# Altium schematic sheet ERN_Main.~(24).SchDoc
size A; SheetNumber: 1; SheetTotal: 1; SPICEModelCacheDBTNACQE: <root> / <DocumentId>DBTNACQE</DocumentId> / <CacheFrame Number="0"> / <Model Name="1n5400" Kind="MDL"> / <Text>*1N5400 MCE / * 50V 3A Si Rectifier pkg:DO-201 1,2 / .MODEL 1N5400 D(IS=2.68E-12 RS=0.00977 N=1.17 TT=1.44E-5 CJO=1.24E-10 / + VJ=0.6 M=0.333 BV=66.6 IBV=1E-5 )</Text> / </Model> / <Model Name="led2" Kind="MDL"> / <Text>*Typ RED,GREEN,YELLOW,AMBER GaAs LED: Vf=2.1V Vr=4V If=40mA trr=3uS / *LED Pinout: 1=A, 2=K / .MODEL LED2 D (IS=93.1P RS=42M N=4.61 BV=4 IBV=10U / + CJO=2.97P VJ=.75 M=.333 TT=4.32U)</Text> / </Model> / <Model Name="irf1010" Kind="CKT"> / <Text>*IRF1010 MCE 4-2-96 / *55V  75A .014 ohm HEXFET pkg:TO-220 2,1,3 / .SUBCKT IRF1010  10 20 40 40 / M1   1  2  3  3  DMOS L=1U W=1U / RD  10  1  5.65M / RS  30  3  1.35M / RG  20  2  12.1 / CGS  2  3  2.15N / EGD 12  0  2  1  1 / VFB 14  0  0 / FFB  2  1  VFB  1 / CGD 13 14  4.49N / R1  13  0  1 / D1  12 13  DLIM / DDG 15 14  DCGD / R2  12 15  1 / D2  15  0  DLIM / DSD  3 10  DSUB / LS  30 40  7.5N / .MODEL DMOS NMOS (LEVEL=3 THETA=60M VMAX=114K ETA=2M VTO=3 KP=19.4) / .MODEL DCGD D (CJO=4.49N VJ=.6 M=.68) / .MODEL DSUB D (IS=311N N=1.5 RS=8.67M BV=55 CJO=4.08N VJ=.8 M=.42 TT=100N) / .MODEL DLIM D (IS=100U) / .ENDS IRF1010</Text> / </Model> / </CacheFrame> / </root>
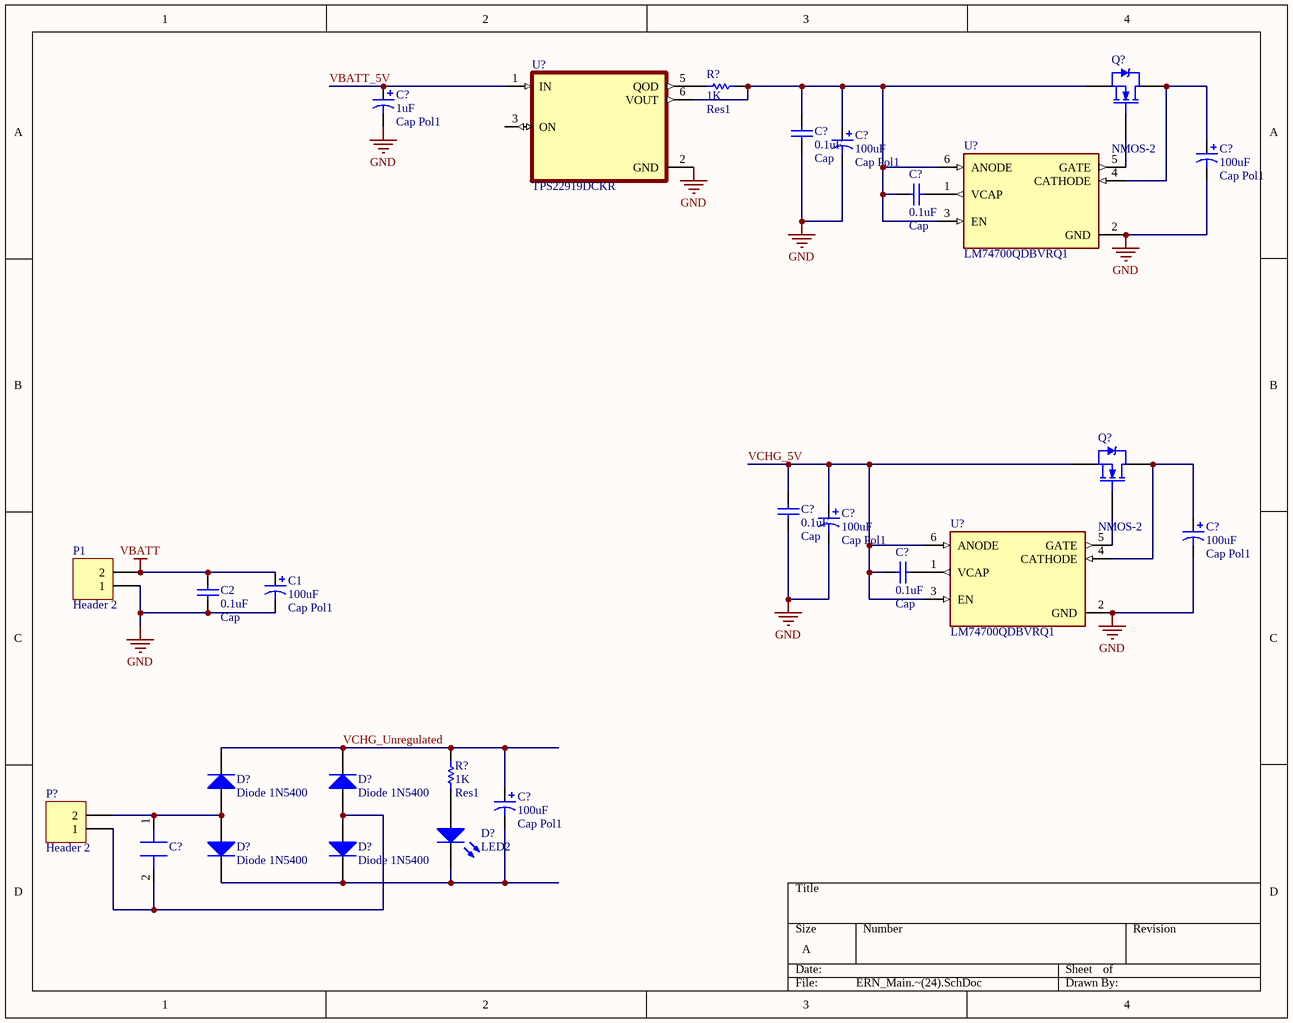
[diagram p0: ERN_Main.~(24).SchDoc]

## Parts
(Parts that share a designator on the sheet are numbered #1, #2 ... from top to bottom, then left to right.)
C1  Cap Pol1  value 100uF  [RB7.6-15]
C2  Cap  value 0.1uF  [RAD-0.3]
C?#1  Cap Pol1  value 1uF  [RB7.6-15]
C?#2  Cap  value 0.1uF  [RAD-0.3]
C?#3  Cap Pol1  value 100uF  [RB7.6-15]
C?#4  Cap Pol1  value 100uF  [RB7.6-15]
C?#5  Cap  value 0.1uF  [RAD-0.3]
C?#6  Cap  value 0.1uF  [RAD-0.3]
C?#7  Cap Pol1  value 100uF  [RB7.6-15]
C?#8  Cap Pol1  value 100uF  [RB7.6-15]
C?#9  Cap  value 0.1uF  [RAD-0.3]
C?#10  Cap Pol1  value 100uF  [RB7.6-15]
C?#11  C2220C944K5GLCAUTO  [CAPC5750X39M]  (value not drawn)
D?#1  Diode 1N5400  [DO-201AD]
D?#2  Diode 1N5400  [DO-201AD]
D?#3  LED2  [3.2X1.6X1.1]
D?#4  Diode 1N5400  [DO-201AD]
D?#5  Diode 1N5400  [DO-201AD]
P1  Header 2  [HDR1X2]
P?  Header 2  [HDR1X2]
Q?#1  NMOS-2  [TO-220AB]
Q?#2  NMOS-2  [TO-220AB]
R?#1  Res1  value 1K  [AXIAL-0.3]
R?#2  Res1  value 1K  [AXIAL-0.3]
U?#1  TPS22919DCKR  [SOT65P210X110-6N]
U?#2  LM74700QDBVRQ1  [SOT95P280X145-6N]
U?#3  LM74700QDBVRQ1  [SOT95P280X145-6N]

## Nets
GND: C1.2 C2.1 C?#1.2 C?#2.1 C?#3.2 C?#4.2 C?#6.1 C?#7.2 C?#8.2 P1.1 U?#1.2(GND) U?#2.2(GND) U?#3.2(GND)
VBATT: C1.1 C2.2 P1.2
VBATT_5V: C?#1.1 U?#1.1(IN)
VCHG_5V: C?#6.2 C?#7.1 C?#9.2 Q?#2.3(S) U?#3.3(EN) U?#3.6(ANODE)
VCHG_Unregulated: C?#10.1 D?#1.2(K) D?#2.2(K) R?#2.2
NetC?#2_2: C?#2.2 C?#3.1 C?#5.2 Q?#1.3(S) R?#1.1 U?#1.6(VOUT) U?#2.3(EN) U?#2.6(ANODE)
NetC?#4_1: C?#4.1 Q?#1.2(D) U?#2.4(CATHODE)
NetC?#5_1: C?#5.1 U?#2.1(VCAP)
NetC?#8_1: C?#8.1 Q?#2.2(D) U?#3.4(CATHODE)
NetC?#9_1: C?#9.1 U?#3.1(VCAP)
NetC?#10_2: C?#10.2 D?#3.2(K) D?#4.2(K) D?#5.2(K)
NetC?#11_1: C?#11.1 D?#1.1(A) D?#4.1(A) P?.2
NetC?#11_2: C?#11.2 D?#2.1(A) D?#5.1(A) P?.1
NetD?#3_1: D?#3.1(A) R?#2.1
NetQ?#1_1: Q?#1.1(G) U?#2.5(GATE)
NetQ?#2_1: Q?#2.1(G) U?#3.5(GATE)
NetR?#1_2: R?#1.2 U?#1.5(QOD)

Not connected (* = marked no-connect by the designer): U?#1 3(ON)

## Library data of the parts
C1 C?#1 C?#3 C?#4 C?#7 C?#8 C?#10 = Cap Pol1: Polarized Capacitor (Radial)
C2 C?#2 C?#5 C?#6 C?#9 = Cap: Capacitor
C?#11 = C2220C944K5GLCAUTO: CAP CER 0.94UF 50V C0G/NP0 2220
D?#1 D?#2 D?#4 D?#5 = Diode 1N5400: 3 Amp General Purpose Rectifier
D?#3 = LED2: Typical RED, GREEN, YELLOW, AMBER GaAs LED
P1 P? = Header 2: Header, 2-Pin
Q?#1 Q?#2 = NMOS-2: N-Channel Power MOSFET; Note: Pin 2 is electrically connected to pin 4.
R?#1 R?#2 = Res1: Resistor
U?#1 = TPS22919DCKR: 5.5-V, 1.5-A, 90-mÎ© load switch with adj. output discharge; MF: Texas Instruments
U?#2 U?#3 = LM74700QDBVRQ1: 3.2-V to 65-V, 80-uA IQ automotive ideal diode controller; MF: Texas Instruments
